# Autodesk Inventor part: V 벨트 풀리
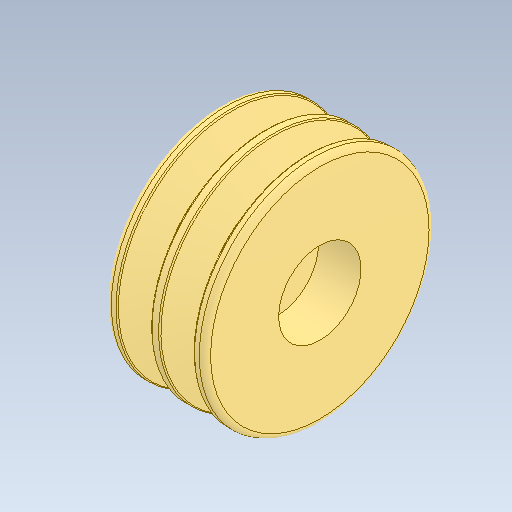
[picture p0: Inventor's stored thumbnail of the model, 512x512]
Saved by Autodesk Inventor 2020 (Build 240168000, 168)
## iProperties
Created: 2024-09
Part Number: V 벨트 풀리
Material: 강철, 주조
Document SubType Name: Modeling
Designer: oem
Density: 7.85 g/cm^3
Appearance: 기본값
Author: jhkim
Sending System: Autodesk Inventor 2025
Preprocessor: ST-DEVELOPER v20
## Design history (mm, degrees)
feature "솔리드1"
node "솔리드2"
